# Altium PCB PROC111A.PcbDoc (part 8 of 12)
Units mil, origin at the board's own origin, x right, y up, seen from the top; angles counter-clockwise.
Board outline 7700 x 2300 mil, 6 copper layers (Top Layer, GND 1, SIG 1, SIG 2, GND 2, Bottom Layer), stack 61.062 mil thick; 841 components, 632 nets, 2914 pads, 1627 vias.
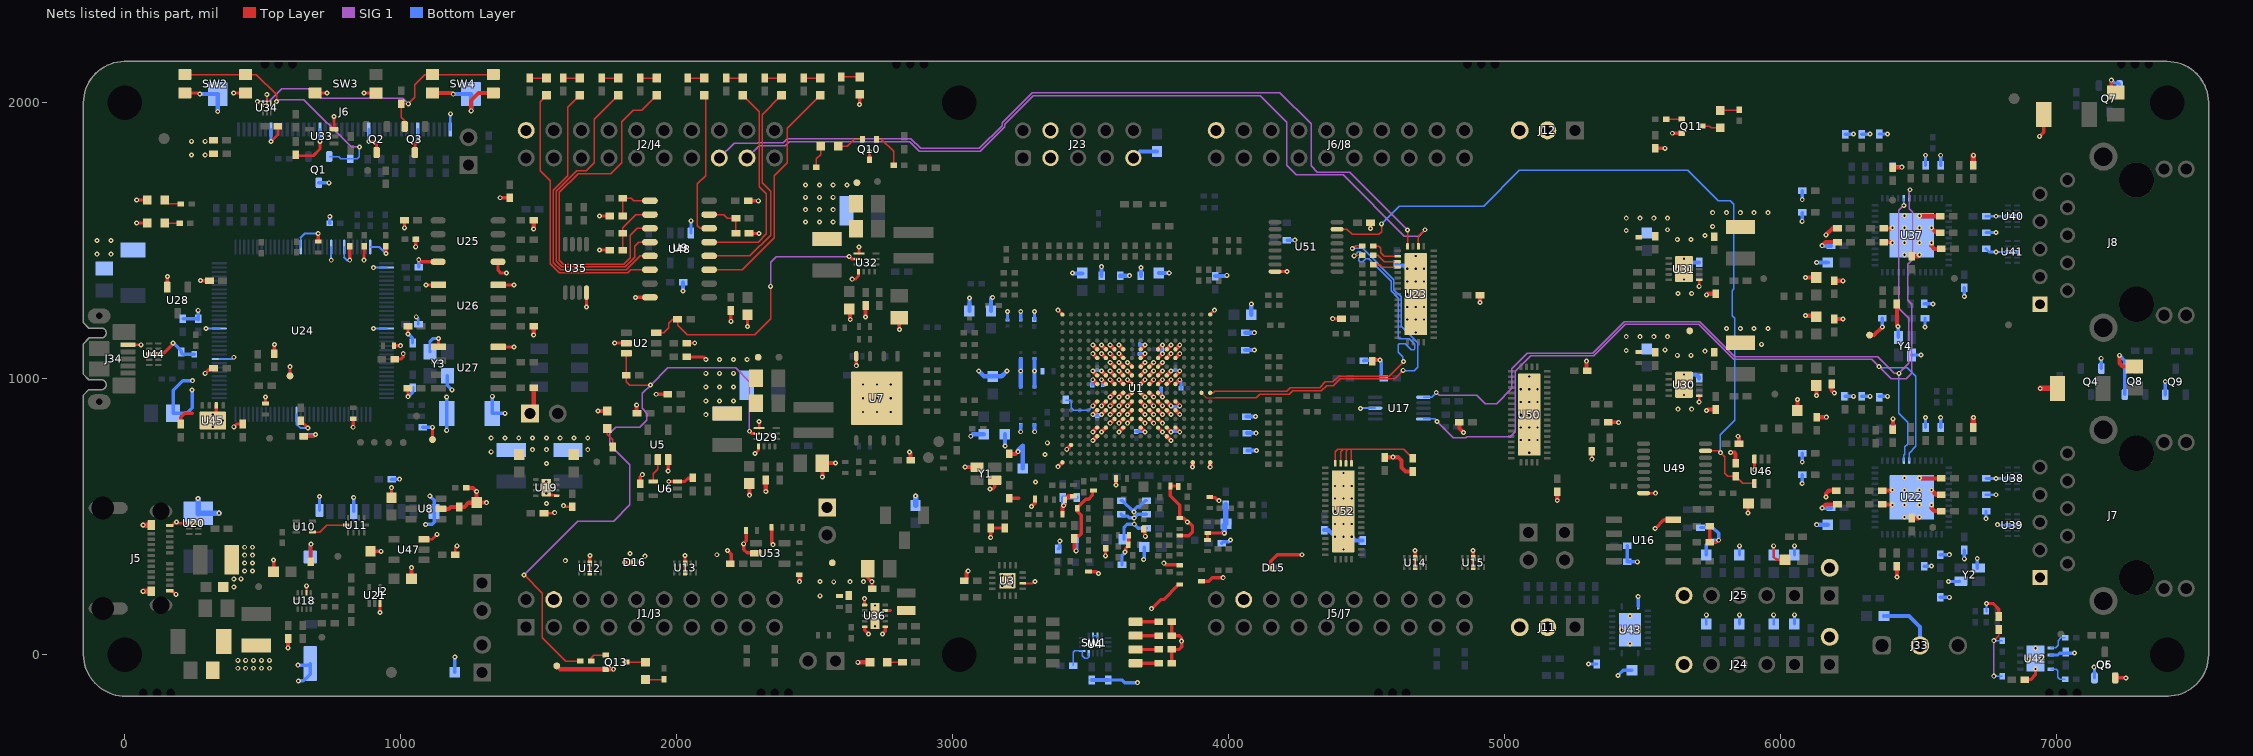
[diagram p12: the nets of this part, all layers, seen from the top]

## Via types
v1: diameter 18, hole 8, Top Layer to Bottom Layer, tented both sides, 1523 vias
v2: diameter 19.68, hole 7.87, Top Layer to Bottom Layer, tented both sides, 104 vias

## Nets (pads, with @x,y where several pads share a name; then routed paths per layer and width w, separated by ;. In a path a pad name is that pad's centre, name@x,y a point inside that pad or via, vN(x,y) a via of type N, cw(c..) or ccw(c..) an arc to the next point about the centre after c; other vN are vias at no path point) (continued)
GND: C1.2 C2.2 C3.2 C4.2 C5.2 C6.2 C7.2 C8.2 C9.2 C10.2 C11.2 C12.2 C13.2 C14.2 C15.2 C16.2 C17.2 C18.2 C19.1 C20.1 C21.1 C22.1 C23.2 C24.2 C25.2 C26.2 C27.2 C28.2 C29.1 C30.1 C31.1 C32.1 C33.2 C34.2 C35.2 C36.2 C37.2 C38.2 C39.1 C40.1 C41.1 C42.1 C43.1 C44.1 C45.1 C46.1 C47.1 C48.2 C49.2 C50.2 C51.2 C52.2 C53.2 C54.2 C55.2 C56.2 C57.1 C58.2 C59.2 C60.1 C61.1 C62.1 C63.2 C64.1 C65.1 C66.1 C67.2 C68.2 C69.2 C70.1 C71.1 C72.1 C73.1 C74.1 C75.1 C81.1 C82.1 C83.1 C84.1 C85.1 C86.1 C87.1 C88.1 C89.2 C90.2 C91.2 C92.1 C93.1 C94.1 C95.1 C96.1 C97.1 C98.2 C99.1 C100.1 C101.2 C102.2 C103.2 C104.2 C105.2 C106.2 C107.2 C108.2 C109.2 C110.2 C111.1 C112.2 C113.2 C114.2 C115.2 C116.2 C117.2 C118.2 C119.2 C120.2 C121.2 C122.2 C123.2 C124.2 C125.2 C126.2 C127.2 C128.2 C129.2 C130.2 C131.2 C132.2 C133.2 C136.1 C137.1 C138.1 C157.2 C158.2 C159.2 C160.2 C161.2 C162.2 C163.2 C164.2 C165.2 C166.2 C167.2 C168.2 C169.2 C170.2 C171.2 C172.2 C173.2 C174.2 C175.2 C176.2 C177.2 C178.2 C179.2 C180.2 C181.1 C182.1 C183.1 C184.1 C185.2 C186.2 C187.2 C188.2 C189.2 C190.2 C191.2 C192.2 C193.2 C194.2 C195.2 C196.2 C197.2 C198.2 C199.2 C200.2 C201.2 C202.2 C203.2 C204.2 C205.2 C206.2 C207.2 C208.2 C209.2 C210.2 C211.2 C212.2 C213.2 C214.2 C215.2 C216.2 C217.2 C218.2 C219.2 C220.2 C221.2 C222.2 C223.1 C224.2 C225.1 C226.1 C229.1 C234.2 C235.1 C236.2 C237.2 C238.1 C239.1 C240.1 C241.1 C242.1 C243.1 C244.1 C245.1 C246.1 C247.1 C248.2 C249.2 C250.2 C251.1 C252.1 C253.2 C254.2 D1.1 D2.1 D4.1 D6.1 D15.2 D16.2 J1/J3.22 J2.6 J2.10 J2.S1 J2.S2 J2.S3 J2.S4 J2/J4.20 J5.A1 J5.A12 J5.B1 J5.B12 J5/J7.62 J6.7 J6.16 J6.25 J6.34 J6.40 J6.41 J6.42 J6/J8.60 J7.1 J8.1 J11.2 J11.3 J12.2 J12.3 J15.2 J16.2 J17.1 J18.1 J23.3 J23.4 J23.9 J24.5 J25.5 J33.2 Q1.3 Q2.3 Q3.3 Q4.2 Q5.2 Q6.2 Q7.2 Q8.2 Q9.2 Q10.3 Q11.2 Q13.2 R2.1 R6.1 R20.2 R21.1 R22.1 R23.1 R24.1 R25.1 R32.2 R39.1 R44.1 R95.1 R96.1 R97.1 R98.2 R107.1 R120.1 R121.1 R122.1 R123.1 R124.1 R125.1 R126.1 R127.1 R128.1 R148.1 R152.1 R154.1 R160.1 R161.1 R163.1 R202.1 R215.1 R216.1 R217.1 R218.1 R219.1 R220.1 R221.1 R222.1 R223.1 R250.1 R254.2 R255.2 R256.1 R274.1 R275.1 R276.1 R278.1 R289.1 R290.1 R293.1 R294.1 R299.2 R300.1 R304.1 R307.1 R316.2 R321.1 R322.1 R323.1 R373.1 R375.1 SW2.1 SW2.3 SW3.1 SW3.3 SW4.1 SW4.3 TP6.1 TP13.1 TP14.1 TP15.1 TP16.1 TP17.1 U1.A1 U1.A18 U1.E5 U1.E6 U1.E7 U1.E8 U1.E10 U1.E12 U1.E13 U1.E14 U1.F5 U1.F6 U1.F7 U1.F8 U1.F10 U1.F12 U1.F13 U1.F14 U1.G7 U1.G8 U1.G9 U1.G10 U1.G11 U1.G12 U1.H5 U1.H6 U1.H7 U1.H8 U1.H9 U1.H10 U1.H11 U1.H12 U1.H13 U1.H14 U1.J5 U1.J6 U1.J7 U1.J8 U1.J9 U1.J10 U1.J11 U1.J12 U1.J13 U1.J14 U1.K7 U1.K8 U1.K9 U1.K10 U1.K11 U1.K12 U1.L5 U1.L6 U1.L7 U1.L8 U1.L9 U1.L10 U1.L11 U1.L12 U1.L13 U1.L14 U1.M5 U1.M6 U1.M7 U1.M8 U1.M9 U1.M10 U1.M11 U1.M12 U1.M13 U1.M14 U1.N7 U1.N8 U1.N9 U1.N10 U1.N11 U1.N12 U1.P5 U1.P6 U1.P8 U1.P10 U1.P12 U1.P13 U1.P14 U1.R5 U1.R13 U1.T2 U1.V1 U1.V16 U1.V18 U2.2 U3.6 U3.17@3198.05,268.7 U4.10 U4.11 U5.3 U6.3 U7.4 U7.9 U8.2 U9.3 U12.3@1685,298.04 U12.8@1685,330.91 U13.3@2030,298.56 U13.8@2030,331.44 U14.3@4675,317.68 U14.8@4675,350.55 U15.3@4885.4,317.82 U15.8@4885.4,350.69 U16.4 U17.3 U18.10 U19.5 U19.9 U20.3@233.41,476.95 U20.8@266.29,476.95 U21.3 U22.49 U23.43 U25.5 U26.4 U27.4 U29.4 U29.7 U30.6 U30.11 U31.6 U31.11 U32.4 U32.7 U33.3 U34.2 U35.4 U36.1 U36.5 U36.6 U36.11@2717.72,141.07 U37.49 U38.3@6856.02,638.94 U38.8@6823.14,638.94 U39.3@6855.75,469.6 U39.8@6822.87,469.6 U40.3@6856.02,1588.94 U40.8@6823.14,1588.94 U41.3@6855.75,1459.6 U41.8@6822.87,1459.6 U42.2 U42.9 U43.11 U43.21 U46.3 U47.3 U48.16 U49.8 U50.43 U51.8 U52.43 U53.2 Y1.2 Y1.4 Y2.2 Y2.4 Y4.2 Y4.4 | length 18831.1
  Top Layer w6: U34.2@515,1996.97 v1@515,2029.53
  Top Layer w7: U18.10@658.07,224.61 v1(658.07,250)
  Top Layer w8: v1(514.53,2030) v1@515,2029.53 ; U3.6@3253.17,258.86 3288.32,258.86 3295.5,266.04 v1(3298.21,266.04)
  Top Layer w10: v1(187.46,481.61) 189.63,481.61 194.29,476.95 U20.3@233.41,476.95 U20.8@266.29,476.95 ; v1(530,1859.61) 555.62,1885.22 C181.1@555.62,1915 ; C182.1@619.3,1808.19 682.83,1808.19 707.17,1832.52 v1(707.17,1859.61) ; v1(925,152.93) U21.3@924.98,185.87 ; v1(965.86,605.32) 965.86,569.53 C67.2@966.44,568.95 ; U47.3@1083.63,418.4 1113.4,418.4 v1(1131.5,436.5) ; R299.2@1197.12,362.5 1197.12,388.62 v1(1203.5,395) ; R98.2@1518.62,513.27 1553.78,513.27 1555.51,515 v1(1557.67,515) ; U19.9@1526.92,605.91 1526.92,592.13 1539.64,579.41 1549.16,579.41 1550.3,578.27 1557.67,578.27 1559.56,576.38 U19.5@1564.33,576.38 ; v1(1590,540.32) 1593.94,536.38 C109.2@1621.58,536.38 ; v1(2283.37,728.82) 2296.36,741.81 U29.7@2296.36,755.26 ; U29.4@2298.33,821.21 v1(2298.33,845.01) ; v1(2635.5,1361) 2647,1361 2658.03,1372.03 U32.7@2658.03,1387.88 ; U32.4@2660,1453.83 v1(2660,1477.63) ; v1(3381.39,1248.54) U1.A1@3397.13,1232.8 ; v1(3553.53,358.51) 3553.58,358.55 R307.1@3553.58,385.13 ; U1.A18@3932.57,1232.8 v1(3948.31,1248.54) ; U51.8@4167.8,1388.35 v1(4210.59,1388.35) ; v1(5315.31,708.62) R289.1@5315.31,737.92 ; U49.8@5502.8,585.66 v1(5545.59,585.66) ; v1(5704.25,915.8) U30.6@5704.25,939.06 ; v1(5704.25,1334.99) U31.6@5704.25,1358.25 ; v1(5974.18,395) 5974.18,354.64 5984.15,344.67 C221.2@6015.63,344.67
  Top Layer w11: J5.A12@163.07,231.89 170.95,231.89 183.61,219.23 v1(185.37,219.23) ; J5.A1@163.07,468.11 170.95,468.11 183.1,480.27 186.12,480.27 v1(187.46,481.61)
  Top Layer w12: SW2.1@217.32,2035.35 267,2035.35 270.21,2032.15 v1(271.83,2032.15) ; v1(394.55,2035.35) SW2.3@437.8,2035.35 ; C101.2@539.29,304.11 v1(539.29,343.25) ; R97.1@673.29,337.04 673.77,337.51 673.77,400.18 v1(674.24,400.65) ; SW3.1@689.76,2035.35 v1(733.01,2035.35) ; U33.3@757.66,1903.74 v1(757.66,1950) ; v1(866.99,2035.35) SW3.3@910.24,2035.35 ; v1(884.33,1859.61) 905,1859.61 912.25,1852.35 Q2.3@912.25,1819.78 ; C110.2@890,375.04 v1(927.78,375.04) ; Q3.3@1051.12,1819.78 1051.14,1849.25 v1(1061.5,1859.61) ; U25.5@1352.36,1423.86 1352.36,1393.52 1362.61,1383.27 v1(1383.19,1383.27) ; U27.4@1353.27,1115.27 v1(1410,1115.27) ; U26.4@1353.27,1340 v1(1410,1340) ; v1(1360,1656) R21.1@1395,1656 ; v1(1672.76,1260.12) U35.4@1672.76,1312.4 ; U12.3@1685,298.04 U12.8@1685,330.91 v1(1685,359.48) ; v1(1720,1466.57) R276.1@1757.31,1466.57 ; v1(1720,1589.85) R274.1@1757.31,1589.85 ; v1(1775,1129.45) U2.2@1817.11,1129.45 ; v1(1810,335.1) D16.2@1834.92,335.1 ; v1(1850.43,1295) U48.16@1902.72,1295 ; C64.1@1867.57,620.1 1867.57,645.11 v1(1875,652.54) ; v1(1925.37,944.07) R20.2@1967.18,944.07 ; v1(1968.71,665.97) U5.3@1968.71,707.27 ; v1(1970.87,627.98) U6.3@2002.96,627.98 2029.73,627.98 2041.61,639.85 2057.84,639.85 C63.2@2057.84,641.01 ; U13.3@2030,298.56 U13.8@2030,331.44 v1(2030,360) ; C57.1@2036.02,1129.45 v1(2065,1129.45) ; R6.1@2036.34,1079.13 2094.97,1079.13 2104.1,1070 v1(2105,1070) ; v1@2183.96,378.38 2197.34,364.99 R375.1@2197.34,330.17 ; v1(2195.94,1208.33) C237.2@2195.94,1247.76 ; C254.2@2251.19,450.13 2251.19,412.43 2242.36,403.61 v1(2242.36,401.98) 2242.36,381.45 2254.39,369.42 2285.58,369.42 U53.2@2287.43,367.57 ; v1(2255.95,1189.91) C236.2@2255.95,1232.01 ; R278.1@2258.62,1645 v1(2295.32,1645) ; R275.1@2261.63,1526.55 v1(2298.33,1526.55) ; C253.2@2343.56,461.96 2343.56,405.03 2348.12,400.47 v1(2348.12,398.85) ; U7.4@2650,1082.08 2650,1047.93 v1(2650.41,1047.52) ; v1(2655.91,-27.34) v1@2656.41,-26.84 ; v1(2662.21,1993.35) 2662.72,1993.87 D4.1@2662.72,2030.75 ; U36.5@2680.31,101.69 2680.7,101.69 2680.7,89.17 v1(2695,74.87) ; U36.1@2680.31,182.8 v1(2680.31,203.41) ; C185.2@2691.5,312.4 2691.5,280 v1(2706.5,265) 2707.19,264.31 2707.19,240.06 C186.2@2707.87,239.37 ; Q10.3@2698,1793.6 v1(2698,1824.32) ; v1(2745,74.87) 2755.12,84.98 U36.6@2755.12,101.69 ; R160.1@2806.47,1220.85 2806.47,1178.5 v1(2806.79,1178.18) ; v1(3135,601.21) 3144.48,601.21 3151.99,608.72 Y1.2@3151.99,632.59 ; v1(3137.35,425.17) 3137.47,425.29 C48.2@3137.47,459.62 R2.1@3187.66,459.62 ; C58.2@3205,567.59 3239.33,567.59 3239.46,567.47 ; C91.2@3440,421.38 3440,425.32 3445.81,431.13 3457.72,431.13 3465.21,438.61 3465.21,505.29 3452.34,518.16 3452.34,529.32 C96.1@3450.84,530.82 ; C96.1@3450.84,532.82 3481.6,563.57 3489.68,563.57 3489.92,563.82 3491.78,563.82 3505.99,578.03 3505.99,593.67 3507.49,595.17 C97.1@3509.8,595.17 ; C251.1@3491.36,301.22 C251.1@3491.62,301.22 3519.2,301.22 3526.22,294.2 v1(3527.84,294.2) ; v1@3590.83,616.61 3590.83,638.44 C93.1@3590.94,638.55 ; v1@3625.31,371.95 3626.45,373.1 3626.45,385.27 3634.1,392.92 3634.1,396.92 C87.1@3635.6,398.42 ; C87.1@3635.6,398.92 3637.1,400.42 3637.1,426.29 3638.81,428 C88.1@3638.81,432.5 ; R44.1@3691.48,454.12 3695.32,450.27 3695.32,432.97 3697.37,430.93 v1(3697.37,429.3) ; v1(3719.97,167.18) 3753.12,200.33 3763.78,200.33 3817.59,254.13 C86.1@3822.09,254.13 ; v1(3764.37,331.78) 3765.99,331.78 3771.77,326 3820.59,326 C81.1@3822.09,324.5 ; R22.1@3793.62,-30.49 R23.1@3793.62,19.51 3819.81,19.51 3828.97,28.67 v1(3828.97,49.16) 3828.43,49.69 3828.43,62.48 3821.4,69.51 R24.1@3793.62,69.51 R25.1@3793.62,119.51 ; C84.1@3816.76,609.98 3815.26,611.49 C82.1@3788.34,611.49 3788.34,575.68 3822.33,541.69 C83.1@3822.33,496.02 3823.83,494.52 3837.54,494.52 3849.25,482.82 v1(3849.64,480.71) ; C74.1@3822.33,431.86 3855.02,431.86 3868.58,445.42 3868.58,465.5 3855.84,478.24 3853.82,478.25 v1(3849.64,480.71) ; v1@3849.25,478.62 v1(3849.64,480.71) ; C85.1@3901.07,266.72 3927.21,266.72 3939.99,279.5 v1(3979.74,279.5) ; C75.1@3922.62,418.13 3922.88,418.4 3922.88,441.3 C72.1@3923.15,441.57 3923.48,441.23 3983.38,441.23 v1(3983.72,440.9) ; C73.1@3931.07,571.48 3932.57,569.98 3949.2,569.98 3959.77,559.4 3963.34,559.4 v1(3964.49,558.25) ; D15.2@4150.71,315.32 4151.6,316.2 4151.6,338.97 4175.15,362.52 v1(4265,362.52) ; v1(4376.3,1217.86) 4376.37,1217.93 R290.1@4408.11,1217.93 ; U14.3@4675,317.68 U14.8@4675,350.55 v1(4675,377.91) ; v1(4885,377.91) 4885.4,377.5 U15.8@4885.4,350.69 U15.3@4885.4,317.82 ; v1@5189.88,559.09 v1(5190,558.97) ; R294.1@5375,842.02 5412.09,842.02 v1(5412.51,841.6) ; v1(5544.94,457.56) 5576.52,489.14 U16.4@5610.08,489.14 ; R304.1@5545.31,1835.02 v1(5580,1835) ; v1(5606.81,1889.68) Q11.2@5640.6,1889.68 ; R323.1@5742.56,465 R321.1@5742.56,406.99 5766.9,406.99 v1(5774.91,415) ; v1(5881.36,513.38) 5881.36,547.14 C248.2@5882.6,548.38 ; v1(5904.41,670.59) U46.3@5904.41,709.29 ; v1(6745,185.87) 6769.4,185.87 6790,165.27 C222.2@6790,138.62 ; C226.1@6883.62,-89.6 6905.4,-89.6 6922.8,-72.2 v2(6922.8,-50.95) ; v1(6937.71,1878.68) 6952.48,1893.44 C247.1@6952.48,1956.97 ; v1(7197.42,2081.89) 7197.42,2053.71 R255.2@7214.16,2036.97 ; Q5.2@7211.4,-83.58 v1(7250,-83.58)
  Top Layer w13: U1.P12@3743.59,823.35 v1(3759.34,807.6) ; U1.P13@3775.09,823.35 v1(3790.83,807.6) ; U1.P14@3806.58,823.35 v1(3822.33,807.6)
  Top Layer w15: R95.1@591.65,58.85 591.71,58.8 591.71,25.37 v1(591.77,25.31) ; C249.2@1038.36,275.41 v1(1038.36,315.6) ; SW4.1@1114.76,2035.35 1185.13,2035.35 1189.19,2031.3 v1(1190,2031.3) ; U8.2@1145.16,528.6 1173.99,528.6 1180.8,535.41 C69.2@1212.1,535.41 1230.37,535.41 1246.06,551.1 1274.7,551.1 C68.2@1274.76,551.16 ; R39.1@1236.92,604.8 1261.3,604.8 1274.76,591.35 C68.2@1274.76,551.16 ; v1(1255,1970.99) 1255,2008.4 1281.95,2035.35 SW4.3@1335.24,2035.35 ; v1(1310.42,551.16) C68.2@1274.76,551.16 ; J17.1@1468.62,873.77 1481.5,886.64 C136.1@1481.5,967.23 ; v1(1481.5,1158.81) C137.1@1481.5,1190 ; v1(1481.5,1542.68) C138.1@1481.5,1573.86 ; TP13.1@1565,-40 1577.2,-52.2 Q13.2@1742.6,-52.2 v1(1771.18,-52.2) ; v1(1714.39,883.2) D2.1@1748.27,883.2 ; v1(1854.54,905.56) 1854.54,875.93 C65.1@1855.6,874.86 ; C160.2@2262.84,620.19 2262.84,578.44 v1(2263.01,578.27) ; R154.1@2322.33,633.06 2322.33,591.32 v1(2322.51,591.14) ; v1(2444.32,265) R373.1@2444.32,290.17 ; v1(2527.33,644.21) R148.1@2527.33,694.68 2574.68,694.68 v1(2575,695) ; C177.2@2624.51,1252.8 2627.87,1249.45 2627.87,1215.22 v1(2628.44,1214.64) ; v1@2656.41,-26.84 D6.1@2700,-26.84 ; R163.1@2684,1265.68 2684,1223.93 v1(2684.18,1223.76) ; v1(2843.31,735.26) 2847.24,731.32 C66.1@2847.24,704.15 ; C60.1@3041.38,268.33 3045.32,268.33 3049.63,272.64 3049.63,297.03 3055.7,303.1 v1(3055.7,303.91) ; v1(3045,680) 3045.16,679.84 Y1.4@3088.01,679.84 ; C59.2@3205,727.96 3227.36,727.96 3235.25,735.85 v1(3236.07,735.85) ; v1(3285.55,537.72) 3285.55,538.53 3297.3,550.27 C92.1@3297.3,564.5 ; v1(3381.39,681.61) U1.V1@3397.13,697.36 ; C252.1@3397.4,508.89 3397.4,535.41 3401.66,539.67 v1(3401.66,540.48) 3401.66,541.29 3406.75,546.38 C94.1@3406.75,562.35 3406.75,566.85 3411.25,566.85 3418.99,574.59 C95.1@3437.53,574.59 ; v1(3412.88,744.61) U1.T2@3428.63,760.35 ; C91.2@3440,421.38 3440.77,420.61 3440.77,383.99 3447.17,377.59 v1(3447.17,376.78) ; v1(3507.37,776.1) U1.R5@3523.12,791.85 ; v1(3507.37,807.6) U1.P5@3523.12,823.35 ; v1(3507.37,870.59) U1.M5@3523.12,886.34 ; v1(3507.37,902.09) U1.L5@3523.12,917.83 ; v1(3507.37,996.57) U1.J5@3523.12,980.83 ; v1(3507.37,1028.07) U1.H5@3523.12,1012.32 ; v1(3507.37,1091.06) U1.F5@3523.12,1075.32 ; v1(3507.37,1122.56) U1.E5@3523.12,1106.81 ; v1(3538.87,807.6) U1.P6@3554.61,823.35 ; v1(3538.87,870.59) U1.M6@3554.61,886.34 ; v1(3538.87,902.09) U1.L6@3554.61,917.83 ; v1(3538.87,996.57) U1.J6@3554.61,980.83 ; v1(3538.87,1028.07) U1.H6@3554.61,1012.32 ; v1(3538.87,1091.06) U1.F6@3554.61,1075.32 ; v1(3538.87,1122.56) U1.E6@3554.61,1106.81 ; v1(3570.36,839.09) U1.N7@3586.11,854.84 ; v1(3570.36,870.59) U1.M7@3586.11,886.34 ; v1(3570.36,902.09) U1.L7@3586.11,917.83 ; v1(3570.36,933.58) U1.K7@3586.11,949.33 ; v1(3570.36,996.57) U1.J7@3586.11,980.83 ; v1(3570.36,1028.07) U1.H7@3586.11,1012.32 ; v1(3570.36,1059.57) U1.G7@3586.11,1043.82 ; v1(3570.36,1091.06) U1.F7@3586.11,1075.32 ; v1(3570.36,1122.56) U1.E7@3586.11,1106.81 ; v1(3601.86,807.6) U1.P8@3617.61,823.35 ; v1(3601.86,839.09) U1.N8@3617.61,854.84 ; v1(3601.86,870.59) U1.M8@3617.61,886.34 ; v1(3601.86,902.09) U1.L8@3617.61,917.83 ; v1(3601.86,933.58) U1.K8@3617.61,949.33 ; v1(3601.86,996.57) U1.J8@3617.61,980.83 ; v1(3601.86,1028.07) U1.H8@3617.61,1012.32 ; v1(3601.86,1059.57) U1.G8@3617.61,1043.82 ; v1(3601.86,1091.06) U1.F8@3617.61,1075.32 ; v1(3601.86,1122.56) U1.E8@3617.61,1106.81 ; v1(3633.35,839.09) U1.N9@3649.1,854.84 ; v1(3633.35,870.59) U1.M9@3649.1,886.34 ; v1(3633.35,902.09) U1.L9@3649.1,917.83 ; v1(3633.35,933.58) U1.K9@3649.1,949.33 ; v1(3633.35,996.57) U1.J9@3649.1,980.83 ; v1(3633.35,1028.07) U1.H9@3649.1,1012.32 ; v1(3633.35,1059.57) U1.G9@3649.1,1043.82 ; U1.P10@3680.6,823.35 v1(3696.35,807.6) ; U1.N10@3680.6,854.84 v1(3696.35,839.09) ; U1.M10@3680.6,886.34 v1(3696.35,870.59) ; U1.L10@3680.6,917.83 v1(3696.35,902.09) ; U1.K10@3680.6,949.33 v1(3696.35,933.58) ; U1.J10@3680.6,980.83 v1(3696.35,996.57) ; U1.H10@3680.6,1012.32 v1(3696.35,1028.07) ; U1.G10@3680.6,1043.82 v1(3696.35,1059.57) ; U1.F10@3680.6,1075.32 v1(3696.35,1091.06) ; U1.E10@3680.6,1106.81 v1(3696.35,1122.56) ; U1.N11@3712.09,854.84 v1(3727.84,839.09) ; U1.M11@3712.09,886.34 v1(3727.84,870.59) ; U1.L11@3712.09,917.83 v1(3727.84,902.09) ; U1.K11@3712.09,949.33 v1(3727.84,933.58) ; U1.J11@3712.09,980.83 v1(3727.84,996.57) ; U1.H11@3712.09,1012.32 v1(3727.84,1028.07) ; U1.G11@3712.09,1043.82 v1(3727.84,1059.57) ; U1.N12@3743.59,854.84 v1(3759.34,839.09) ; U1.M12@3743.59,886.34 v1(3759.34,870.59) ; U1.L12@3743.59,917.83 v1(3759.34,902.09) ; U1.K12@3743.59,949.33 v1(3759.34,933.58) ; U1.J12@3743.59,980.83 v1(3759.34,996.57) ; U1.H12@3743.59,1012.32 v1(3759.34,1028.07) ; U1.G12@3743.59,1043.82 v1(3759.34,1059.57) ; U1.F12@3743.59,1075.32 v1(3759.34,1091.06) ; U1.E12@3743.59,1106.81 v1(3759.34,1122.56) ; U1.R13@3775.09,791.85 v1(3790.83,776.1) ; U1.M13@3775.09,886.34 v1(3790.83,870.59) ; U1.L13@3775.09,917.83 v1(3790.83,902.09) ; U1.J13@3775.09,980.83 v1(3790.83,996.57) ; U1.H13@3775.09,1012.32 v1(3790.83,1028.07) ; U1.F13@3775.09,1075.32 v1(3790.83,1091.06) ; U1.E13@3775.09,1106.81 v1(3790.83,1122.56) ; U1.M14@3806.58,886.34 v1(3822.33,870.59) ; U1.L14@3806.58,917.83 v1(3822.33,902.09) ; U1.J14@3806.58,980.83 v1(3822.33,996.57) ; U1.H14@3806.58,1012.32 v1(3822.33,1028.07) ; U1.F14@3806.58,1075.32 v1(3822.33,1091.06) ; U1.E14@3806.58,1106.81 v1(3822.33,1122.56) ; v1(3868.57,680.7) 3868.57,681.52 3869.43,682.38 3869.43,697.22 U1.V16@3869.57,697.36 ; U1.V18@3932.57,697.36 3932.65,697.28 3932.65,680.79 v1(3932.73,680.7) ; C246.1@4513.43,1567.48 4513.66,1567.25 4513.66,1544.97 v1(4513.89,1544.74) ; C240.1@4520.38,1063.22 4520.38,1063.7 4524.69,1068.01 4547.7,1068.01 v1(4548.27,1068.58) ; C245.1@4565,714.8 4566.1,715.9 v1(4595,715.9) 4613.67,715.9 4626.02,703.55 4626.02,678.46 4640.08,664.4 R256.1@4666.77,664.4 ; C111.1@4835.38,842.82 4835.38,819.7 v1(4850,805.08) ; v1(4910,1276.95) C242.1@4910,1301.95 ; v1@5189.88,559.09 C239.1@5189.88,591.15 ; C238.1@5295.86,1029.87 v1(5295.86,1063.79) ; v1(5730.69,885) 5731.5,885 5735.23,888.74 R152.1@5764.13,888.74 ; v1(5730.69,1304.19) 5731.5,1304.19 5735.23,1307.92 R161.1@5764.13,1307.92 ; v1(5818.5,732.8) 5831.65,732.8 5836.5,727.96 R96.1@5836.5,693.62 ; v1(5844.69,791.85) 5848.62,787.91 C43.1@5848.62,764.8 ; C122.2@6060,885.15 v1(6060,925.06) ; v1(6090,1229.35) 6090.74,1228.61 C114.2@6129,1228.61 ; v1(6090,1367.45) 6090.74,1366.71 C191.2@6129,1366.71 ; v1(6128.93,939.06) C199.2@6128.93,975.48 ; C123.2@6130.09,860.77 v1(6165,860.77) ; v1(6150,532.33) 6162.71,545.04 C133.2@6205.51,545.04 ; v1(6150,1482.33) 6162.71,1495.04 C210.2@6205.51,1495.04 ; v1(6163.62,571.81) 6163.62,585 6173.66,595.04 C119.2@6200.51,595.04 ; v1(6163.62,1521.81) 6186.85,1545.04 C196.2@6205.51,1545.04 ; C200.2@6184,981.36 6184,958.26 v1(6194,948.26) ; C115.2@6194,1216.9 6224.83,1216.9 v1(6225,1217.07) ; C192.2@6194,1355 6224.83,1355 v1(6225,1355.17) ; TP16.1@6321.65,1158.13 6338.28,1158.13 v1(6367.76,1187.61) ; C132.2@6367.56,545.04 6401.07,545.04 6403.04,543.07 v2(6404.31,543.07) ; C118.2@6367.56,595.04 6402.34,595.04 v2(6404.31,597.01) ; C209.2@6372.56,1495.04 6402.34,1495.04 v2(6404.31,1493.07) ; C195.2@6372.56,1545.04 6402.34,1545.04 v2(6404.31,1547.01) ; C116.2@6406.28,818.7 v1(6406.28,855) ; C193.2@6406.28,1765.34 6436.92,1765.34 v1(6438.38,1766.8) ; v1(6420.85,281.38) R126.1@6420.85,321.38 ; R221.1@6420.97,1271.26 6420.97,1193.94 v1(6425,1189.91) ; C130.2@6475,494.09 6497.07,494.09 v2(6502.14,499.17) ; C207.2@6475,1444.09 6497.07,1444.09 v2(6502.14,1449.17) ; v2(6502.14,640.91) 6504.11,638.94 C126.2@6581.79,638.94 ; v2(6502.14,1590.91) 6504.11,1588.94 C203.2@6577.79,1588.94 ; v2(6546.04,543.07) 6546.04,530.77 6555.98,520.83 C124.2@6581.79,520.83 ; v2(6546.04,597.01) 6563.17,579.88 C120.2@6581.79,579.88 ; v2(6546.04,1493.07) 6546.04,1480.77 6555.98,1470.83 C201.2@6581.79,1470.83 ; v2(6546.04,1547.01) 6563.17,1529.88 C197.2@6577.79,1529.88 ; v1(7227.27,1085) 7227.27,1056.56 7238.83,1045 R254.2@7280.57,1045
  Top Layer w20: v1(66.53,229.92) J5.B1@96.14,229.92 ; v1(66.53,470.08) J5.B12@96.14,470.08 ; R123.1@6698,823.31 v1(6698,859.61) ; R218.1@6698,1773.31 v1(6698,1809.61) ; v1(6940,965) C235.1@7002.32,965
  Bottom Layer w5.3: C250.2@3409.37,924.52 3411.4,922.5 3424.84,922.5 3428.67,918.66 3428.67,896.58 3428.73,896.52 3428.73,895.6 3437.89,886.44 3482.36,886.44 3482.43,886.51 3491.79,886.51 v1(3507.37,902.09)
  Bottom Layer w6: v1(3524.36,36.33) 3519.49,36.33 3518.82,37.01 3513.2,37.01 3508.2,42.02 U4.10@3508.2,69.28 U4.11@3523.95,69.28 3523.95,37.27 v1@3524.36,36.85
  Bottom Layer w8: v1(4477.36,892.24) 4478.87,893.75 U17.3@4530.08,893.75 ; R250.1@6745,157.24 v1(6745,185.87) ; v1(6780,1459.6) U41.8@6822.87,1459.6 U41.3@6855.75,1459.6
  Bottom Layer w10: J6.7@529.88,1903.35 529.88,1859.73 v1(530,1859.61) ; J6.16@707.05,1903.35 707.05,1859.73 v1(707.17,1859.61) ; J6.25@884.21,1903.35 884.21,1859.73 v1(884.33,1859.61) ; J6.34@1061.38,1903.35 1061.38,1859.73 v1(1061.5,1859.61) ; J6.40@1179.49,1903.35 1179.49,1959.49 v1(1180,1960) ; C211.2@5730,111.5 v1(5730,145) ; C216.2@5850,111.5 v1(5850,145) ; C219.2@5850,361.5 v1(5850,395) ; C215.2@5974.18,111.5 v1(5974.18,145) ; C218.2@5974.18,361.5 v1(5974.18,395) ; C214.2@6049.18,111.5 v1(6049.18,145) ; C217.2@6049.18,361.5 v1(6049.18,395) ; v1(6743.84,493.12) C125.2@6743.84,520.83 ; C121.2@6743.84,579.88 v1(6780,579.88) ; C127.2@6743.84,638.94 v1(6780,638.94) U38.8@6823.14,638.94 U38.3@6856.02,638.94 ; C202.2@6743.84,1470.83 6755.06,1459.6 v1(6780,1459.6) ; C198.2@6743.84,1529.88 v1(6780,1529.88) ; C204.2@6743.84,1588.94 v1(6780,1588.94) U40.8@6823.14,1588.94 U40.3@6856.02,1588.94 ; v1(6785,471.55) 6787.16,471.55 6789.12,469.6 U39.8@6822.87,469.6 U39.3@6855.75,469.6
  Bottom Layer w12: v1(627.94,-37.71) 665.83,-37.71 J2.S3@671.97,-31.57 671.97,-67.88 671.91,-67.94 671.91,-71.01 654.35,-88.57 651.28,-88.57 645.97,-93.88 629.96,-93.88 v1(628.81,-95.03) ; J2.S2@671.97,354.25 671.97,396.76 674.24,399.03 v1(674.24,400.65) ; Q1.3@702.98,1710.51 739.49,1710.51 v1(740,1710) ; J2.10@705.43,523.54 v1(705.43,573.39) ; J2.6@829.45,519.61 v1(829.45,569.45) ; C71.1@965.09,635 966.5,636.41 v1(995.46,636.41) ; v1(1090.34,471.73) 1091.49,472.88 1113.67,472.88 1120.79,480 J2.S1@1120.79,519.61 1120.79,559.21 v1(1105,575) ; J2.S4@1195.59,-63.07 v1@1195.59,-8.02 ; v1(1331.54,936.51) C234.2@1331.54,875 v1(1377.39,875) ; U9.3@2051.37,1528.43 v1@2051.37,1572.46 ; C42.1@3198.24,1215.28 v1(3198.24,1243.66) ; v1(3245.84,808.19) C45.1@3245.84,831.57 ; C21.1@3245.84,1215.28 3245.84,1243.26 v1(3246.24,1243.66) ; C49.2@3295.84,1215.28 3295.84,1243.26 v1(3296.24,1243.66) ; v1(3296.24,1027.95) v1@3296.46,1027.95 ; C38.2@3381.39,383.27 3386.42,388.3 3386.42,410.91 v1(3387.57,412.06) ; C54.2@3504.78,978.1 3504.78,993.99 v1(3507.37,996.57) ; v1(3507.37,870.59) 3510.59,867.37 C56.2@3523,867.37 3535.64,867.37 v1(3538.87,870.59) ; v1(3507.37,1028.07) 3509.37,1030.07 3536.86,1030.07 v1(3538.87,1028.07) ; v1(3538.87,996.57) 3543.17,992.27 C46.1@3543.17,978.1 ; C62.1@3563.69,-91.65 3613.93,-91.65 3623.27,-100.99 v1(3669.32,-100.99) ; C34.2@3610,508.97 3615.81,503.16 3632.43,503.16 3638.63,496.96 3655.92,496.96 v1(3657.07,495.81) 3670.23,508.97 C27.2@3701.69,508.97 ; C36.2@3610,558.97 3613.94,558.97 3655.43,517.48 v1(3656.29,517.48) ; C37.2@3613,326.8 3613,358.02 3625.31,370.33 v1@3625.31,371.95 ; C33.2@3620.38,419.08 3620.38,462.34 3631.18,473.14 v1(3657.41,473.14) 3671.58,458.97 C26.2@3701.69,458.97 ; v1@3657.61,525.07 3668.72,536.19 3674.97,536.19 3697.75,558.97 C28.2@3701.69,558.97 ; C50.2@3664.85,809.09 3694.85,809.09 v1(3696.35,807.6) ; v1@3692.56,344.91 3693.5,345.86 C25.2@3693.5,390.45 ; C22.1@3754.97,965.08 3754.97,937.95 v1(3759.34,933.58) ; v1(3759.34,1091.06) 3755.95,1094.45 C51.2@3755.95,1107.37 3755.95,1119.18 v1(3759.34,1122.56) ; v1(3790.83,807.6) 3793.24,810.01 3819.92,810.01 v1(3822.33,807.6) ; v1(3790.83,902.09) 3794.25,898.67 C47.1@3806.58,898.67 ; v1(3790.83,1028.07) 3792.84,1030.07 3820.33,1030.07 v1(3822.33,1028.07) ; C47.1@3806.58,897.9 C47.1@3806.58,898.67 ; v1(3822.33,902.09) 3818.91,898.67 C47.1@3806.58,898.67 ; v1(3822.33,996.57) 3827.01,991.9 C55.2@3827.01,965.08 ; C24.2@3974.58,404.26 3980.39,410.07 3999.45,410.07 4004.97,415.59 v1(4006.59,415.59) ; R300.1@4212.13,1502.52 v1(4239.19,1502.52) ; R293.1@4488.88,1065.33 4490.98,1067.44 4547.12,1067.44 v1(4548.27,1068.58) 4548.27,1066.96 4552.87,1062.36 4552.87,1007.87 4558.68,1002.06 C100.1@4561.38,1002.06 ; v1(5302.83,-33.58) C223.1@5333.66,-33.58 ; v1(5410,-75) 5428.47,-56.53 C224.2@5460.55,-56.53 ; R316.2@5443.62,395.04 C99.1@5443.62,337.03 v1(5480,337.03) ; U43.11@5483.19,175.27 v1(5483.19,211.28) ; R322.1@5708.93,461.02 5753.98,461.02 5774.91,440.09 v1(5774.91,415) 5745.93,415 5730,399.07 C212.2@5730,361.5 ; v1(6077.6,620.73) 6077.68,620.81 R120.1@6077.68,652.65 ; v1(6077.6,1570.73) 6077.68,1570.81 R215.1@6077.68,1602.65 ; v1(6077.68,699.04) 6077.76,699.12 R121.1@6077.76,730.96 ; v1(6077.68,1649.04) 6077.76,1649.12 R216.1@6077.76,1680.96 ; v1(6130,1421.55) v1@6130.31,1421.24 ; v1(6150,1482.33) v1@6150.37,1481.97 ; R127.1@6233.01,936.59 6263.24,936.59 v1(6263.32,936.51) ; R222.1@6233.01,1886.59 6263.24,1886.59 v1(6263.32,1886.51) ; R128.1@6293.01,936.59 6323.24,936.59 v1(6323.32,936.51) ; R223.1@6293.01,1886.59 6323.24,1886.59 v1(6323.32,1886.51) ; R125.1@6356.28,936.67 6386.51,936.67 v1(6386.59,936.59) ; R217.1@6356.28,1886.67 6386.51,1886.67 v1(6386.59,1886.59) ; v1(6367.76,1187.61) C189.2@6367.76,1220 ; C117.2@6406.28,818.7 v1(6406.28,855) ; C194.2@6406.28,1768.7 6434.85,1768.7 6436.75,1766.8 v1(6438.38,1766.8) ; v1(6425,1189.91) 6425,1151.78 Y4.2@6426.38,1150.4 ; Y4.4@6473.62,1086.42 6473.81,1086.24 v1(6508.19,1086.24) ; C131.2@6520,321.38 v1(6546.04,321.38) ; C208.2@6520,1271.38 v1(6551.84,1271.38) ; v1(6522.24,1187.61) C190.2@6522.24,1220 ; R124.1@6524.39,823.7 v1(6524.39,860) ; R219.1@6524.39,1773.7 v1(6524.39,1810) ; C112.2@6578.01,208.25 v1(6610.4,208.25) ; C113.2@6578.01,362.74 v1(6610.4,362.74) ; R122.1@6579.39,823.7 v1(6579.39,860) ; R220.1@6579.39,1773.7 v1(6579.39,1810) ; v1(6608.1,265.5) 6646.23,265.5 Y2.2@6647.61,266.88 ; v1(6665,347.91) R107.1@6665,379.75 ; v1(6665,1297.91) R202.1@6665,1329.75 ; Y2.4@6711.59,314.12 6711.77,314.31 v1(6711.77,348.69) ; U42.2@6977.91,-0.75 7003.38,-0.75 7010.27,6.14 v1(7063.78,6.14) ; v1(7135,-45) 7135,-46.62 7136.6,-48.22 Q6.2@7136.6,-83.58 ; v1(7160.69,1074.19) 7161.5,1073.38 Q4.2@7161.5,1037.24 ; v1(7197.42,2081.89) 7197.42,2081.82 7207.45,2071.79 7221.59,2071.79 7227.4,2065.98 Q7.2@7227.4,2062.24 ; v1(7227.27,1085) 7246.47,1065.8 Q8.2@7246.47,943.42 ; Q9.2@7392.92,942.15 v1(7392.92,990)
  Bottom Layer w15: v1(271.83,2032.15) 336.12,2032.15 J6.42@336.97,2031.3 336.97,1968.74 v1(336.83,1968.6) ; v1(1190,2031.3) J6.41@1254.29,2031.3 1255.14,2030.45 1255.14,1971.13 v1(1255,1970.99) ; v1(2022.21,1317.82) C70.1@2022.21,1349.2 ; C53.2@3060,1246.25 3060.5,1246.75 v1@3060.5,1285.42 ; v1(3065,791.85) 3072.44,799.29 C2.2@3112.14,799.29 ; v1(3093.98,1027.95) 3112.59,1009.34 3143.76,1009.34 C52.2@3145,1008.1 3146.24,1009.34 3177.41,1009.34 v1(3196.02,1027.95) ; C3.2@3138.51,1246.25 3138.51,1292.01 3141.5,1295 v1(3144.5,1295) ; C1.2@3188.57,799.29 3188.57,757.5 v1(3189.76,756.31) ; v1(3236.07,735.85) 3236.07,741.01 3253.5,758.44 C14.2@3253.5,674.72 ; C40.1@3246.24,972.3 v1(3246.24,1027.95) C44.1@3246.24,1071.06 ; C20.1@3295.84,831.57 3295.84,809.97 3296.81,809 v1(3296.81,808.19) ; v1(3296.24,1027.95) C32.1@3296.24,1071.33 ; C29.1@3296.46,971.9 v1@3296.46,1027.95 ; v1(3401.66,540.48) 3401.66,541.29 3398.76,544.19 3398.76,569.99 C15.2@3398.63,570.13 C7.2@3448.63,570.13 ; v1(3433.43,1382.95) 3435.05,1382.95 3436.44,1381.55 C6.2@3469.13,1381.55 ; C90.2@3445,421.29 3447.17,419.11 v1(3447.17,376.78) ; C61.1@3503.69,-91.65 C62.1@3563.69,-91.65 ; C16.2@3538.87,1373.53 v1(3538.87,1406.28) ; C10.2@3606.08,1373.53 v1(3640,1373.53) ; J23.9@3654.17,1800 3677.68,1823.5 C213.2@3740,1823.5 ; C31.1@3677.84,1089.57 3694.04,1089.57 3695.53,1091.06 v1(3696.35,1091.06) ; C30.1@3677.99,1123.75 3679.18,1122.56 v1(3696.35,1122.56) ; C11.2@3681.66,1373.53 v1(3681.66,1403.28) ; C5.2@3746.57,1382.99 3746.79,1383.2 3783.93,1383.2 v1(3784.14,1383.42) ; C12.2@3950.67,1371.84 3989,1371.84 3991.96,1374.8 v1(3992.77,1374.8) ; C18.2@4059.8,1104.06 v1(4092.55,1104.06) ; C13.2@4059.8,1167.07 v1(4092.55,1167.07) ; C17.2@4064.47,863.32 v1(4097.22,863.32) ; C8.2@4065.8,802.97 v1(4098.55,802.97) ; C9.2@4067.29,740 v1(4100.04,740) ; C4.2@4081.5,1231.81 v1(4081.5,1271.38) ; C243.1@4345.23,451.69 4360.67,451.69 v2(4384.49,427.87) ; v2(4445.51,427.87) 4459.31,414.07 C244.1@4485,414.07 ; C241.1@4608.25,1415.37 4608.25,1414.77 4612.56,1410.46 4632.72,1410.46 4643.65,1399.52 4645.8,1399.52 v2(4646.69,1398.62) ; v2(5649.13,1015.84) 5690.47,1015.84 5696,1010.3 5699.93,1010.3 5704.25,1005.99 C166.2@5704.25,1002.06 ; v2(5649.13,1435.02) 5662.76,1421.39 5704.25,1421.39 C178.2@5704.25,1421.24 ; v1(6130,471.55) 6130.31,471.24 C128.2@6169.86,471.24 ; v1@6130.31,1421.24 C205.2@6169.86,1421.24 ; v1(6150,532.33) 6150.37,531.97 C129.2@6181.89,531.97 ; v1@6150.37,1481.97 C206.2@6181.89,1481.97 ; C220.2@6373.66,140.82 6464.35,140.82 6504.17,100.99 J33.2@6504.17,33.86
  Bottom Layer w20: D1.1@265.72,511.91 v1(265.72,566) ; D1.1@265.82,512.94 v1(341.67,512.94) ; C89.2@2865,541.5 v1(2865,575) ; v1(3983.72,440.9) 3983.72,469.2 C23.2@3989.44,474.92 C35.2@3989.44,543.51
  other v1: 409.45,-48.68 438.11,-48.68 466.77,-48.68 495.43,-48.68 524.1,-48.68 409.45,-20.02 438.11,-20.02 466.77,-20.02 495.43,-20.02 524.1,-20.02 1195.72,-8.21 2518.85,213.58 395,245.67 2568.68,264.31 2518.68,265.31 2627.83,265 2676.41,265 395,274.33 421.27,275.31 434.48,303.65 463.14,303.65 434.48,332.31 463.14,332.31 1595.98,340.87 3691.56,344.91 1885,357.3 434.48,360.97 463.14,360.97 2145,362.52 1830,367.53 3624.31,372.95 2183.76,378.38 434.48,389.63 463.14,389.63 1527.39,548.66 1274.81,591.4 3591.01,615.72 3300,626.33 1527.39,693.3 3334.5,725.36 1327.39,735.51 1477.39,743.3 1527.39,743.3 1677.39,743.3 3342.53,768.09 1327.39,785.51 1377.39,785.51 1427.39,785.51 1477.39,785.51 1527.39,785.51 1577.39,785.51 1627.39,785.51 1677.39,785.51 2105,870 2675,879.5 2725,879.5 2775,879.5 5627.2,890 5677.2,890 2105,920 2155,920 2205,920 2675,929.5 2725,929.5 2775,929.5 2105,970 2155,970 2205,970 2675,979.5 2725,979.5 2775,979.5 2105,1020 2155,1020 2205,1020 2155,1070 2205,1070 2255,1070 5625,1085 5675,1085 5725,1100 5440,1102.62 5580,1105 5930,1125 5440,1152.62 5490,1152.62 5540,1152.62 5590,1152.62 5803.33,1182.62 5853.33,1182.62 5903.33,1182.62 5953.33,1182.62 3060.5,1292.5 5627.2,1309.19 5677.2,1309.19 5625,1504.19 5675,1504.19 5725,1519.19 5440,1536.81 5590,1540 5753.33,1551.81 2466.67,1567.62 2516.67,1567.62 2566.67,1567.62 2051.31,1572.52 5440,1581.81 5490,1581.81 5540,1581.81 5590,1581.81 5753.33,1601.81 5803.33,1601.81 5853.33,1601.81 5903.33,1601.81 5953.33,1601.81 2466.67,1612.62 2516.67,1612.62 2566.67,1612.62 2466.67,1657.62 2516.67,1657.62 2566.67,1657.62 2466.67,1702.62 2516.67,1702.62 2566.67,1702.62 2616.67,1702.62 241.4,1810.39 291.4,1810.39 241.4,1860.39 291.4,1860.39
  other v2: 6900.16,-13.54 6945.43,-13.54 6922.8,23.86 5453.66,40.43 5423.15,90.62 5484.17,90.62 2717.72,103.66 2717.72,141.06 5453.66,140.82 2717.72,178.47 3179.35,250 3216.75,250 3179.35,287.4 3216.75,287.4 4415,381.81 4415,427.87 4384.49,473.94 4415,473.94 4445.51,473.94 6448.21,499.17 4384.49,520 4415,520 4445.51,520 6448.21,543.07 6502.14,543.07 4384.49,566.06 4415,566.06 4445.51,566.06 1526.92,584.25 6448.21,597.01 6502.14,597.01 4384.49,612.13 4415,612.13 4445.51,612.13 1526.92,627.56 6448.21,640.91 4415,658.19 5088.39,731.85 5057.87,777.91 5088.39,777.91 5118.9,777.91 5057.87,823.97 5088.39,823.97 5118.9,823.97 5057.87,870.04 5088.39,870.04 5118.9,870.04 5057.87,916.1 5088.39,916.1 5118.9,916.1 5649.13,941.03 5057.87,962.16 5088.39,962.16 5118.9,962.16 5626.49,978.43 5671.77,978.43 5088.39,1008.22 4677.2,1168.31 4646.69,1214.37 4677.2,1214.37 4707.72,1214.37 4646.69,1260.44 4677.2,1260.44 4707.72,1260.44 4646.69,1306.5 4677.2,1306.5 4707.72,1306.5 4646.69,1352.56 4677.2,1352.56 4707.72,1352.56 5649.13,1360.22 5626.49,1397.62 5671.77,1397.62 4677.2,1398.62 4707.72,1398.62 4677.2,1444.69 6448.21,1449.17 6448.21,1493.07 6502.14,1493.07 6448.21,1547.01 6502.14,1547.01 6448.21,1590.91
GND_XDS: C134.1 C135.1 C139.1 C140.1 C141.1 C142.2 C143.1 C144.1 C145.1 C146.2 C147.1 C148.2 C149.2 C150.1 C151.1 C152.1 C153.1 C154.1 C155.1 C156.2 C227.2 C230.1 C231.2 C232.2 C233.1 C234.1 D3.1 DS3.1 J34.5 R137.1 R145.1 R252.1 R253.2 R261.2 R308.2 R309.2 R310.2 TP24.1 TP26.1 U24.10 U24.17 U24.48 U24.55 U24.58 U24.64 U24.66 U24.80 U24.114 U25.4 U26.5 U27.5 U28.2 U44.3@121.44,1088.92 U44.8@88.56,1088.92 U45.6 U45.9@318.69,848.32 Y3.2 Y3.4 | length 2785.9
  Top Layer w8: J34.5@11.81,1123.37 58.68,1123.37 v1(58.94,1123.11) v1@60,1123.11
  Top Layer w12: v1(43.02,1564.76) D3.1@81.52,1564.76 ; v1(43.02,1647.79) DS3.1@81.52,1647.79 ; U44.8@88.56,1088.92 U44.3@121.44,1088.92 136.77,1088.92 v1@175,1127.15 ; U28.2@154.1,1332 154.1,1370.01 v1(155,1370.91) ; v1(174.9,1129.75) v1@175,1129.65 ; C231.2@202.83,835.89 202.83,861.2 216.63,875 245,875 ; v1(274.55,1355.66) C150.1@306.88,1355.66 ; v1(291.26,1020) 309.73,1038.47 C145.1@321.69,1038.47 ; U45.9@318.69,848.32 331.48,861.12 U45.6@331.48,903.44 ; v1(395,826.17) 404.72,835.89 C233.1@427.56,835.89 ; C232.2@510,910.15 510,933.82 v1(510.2,934.01) ; R252.1@541.97,1090.79 v1(541.97,1124.26) ; TP24.1@598.48,1010.35 v1(598.48,1043.83) ; C147.1@637.63,847.6 v1(663.07,822.16) ; C155.1@648.6,791.85 648.79,792.03 684.53,792.03 v1(690.5,798) ; C148.2@700.81,1497.63 v1(700.81,1526.55) ; v1(815,1429.87) R261.2@815,1480.31 ; v1(827.49,824.51) C146.2@827.49,855.32 ; v1(866.99,1429.87) R308.2@866.99,1480.31 ; v1(945.89,1453.83) R309.2@945.89,1480.31 ; C156.2@975,1120 v1(999.04,1120) ; C153.1@978.62,1071.57 1000.33,1071.57 1008.9,1080.14 v1(1008.9,1090.98) ; v1(1013.31,1547.01) C141.1@1013.31,1573.86 ; v1(1026.17,935.27) C139.1@1026.17,965.27 ; v1(1026.17,1162.74) C140.1@1026.17,1190 ; v1(1054,1478.35) 1054.28,1478.63 R310.2@1054.28,1506.39 ; v1(1065.02,1431.46) 1072.61,1423.86 U25.4@1135.36,1423.86 ; v1(1091.37,1340) U26.5@1136.73,1340 ; TP26.1@1115,779.89 v1(1115,824.22) ; U27.5@1136.73,1115.27 v1(1136.73,1146.18)
  Bottom Layer w7: v1@294.89,1182.24 U24.17@342.35,1182.24 ; U24.10@342.35,1072.01 v1@389.81,1072.01 ; 621.88,836.47 U24.114@621.88,871.22 ; U24.48@637.63,1477.52 637.63,1511.88 ; v1@747.86,1430.06 U24.55@747.86,1477.52 ; 795.11,1439.53 U24.58@795.11,1477.52 ; U24.64@889.59,1477.52 922.2,1477.52 ; v1@901.19,1182.24 U24.80@948.65,1182.24 ; v1@901.19,1402.72 U24.66@948.65,1402.72
  Bottom Layer w8: v1(294.7,1182.06) v1@294.89,1182.24 ; v1@389.81,1072.01 395,1077.2 v1(395,1078.07) ; 621.88,836.47 636.19,822.16 v1(663.07,822.16) ; 637.63,1511.88 652.3,1526.55 v1(700.81,1526.55) ; v1@747.86,1430.06 v1(748.05,1429.87) ; 795.11,1439.53 804.76,1429.87 v1(815,1429.87) ; v1(901,1182.06) v1@901.19,1182.24 ; v1(901,1402.53) v1@901.19,1402.72 ; 922.2,1477.52 v1(945.89,1453.83)
  Bottom Layer w10: v1(1056,1224.46) 1062.81,1217.65 C149.2@1062.81,1197.99
  Bottom Layer w12: v1(174.9,1129.75) 176.3,1129.75 205,1101.05 C135.1@205,1097.11 205,1094.98 210.81,1089.17 R137.1@251.47,1089.17 ; C151.1@210.82,1217.4 261.88,1217.4 C152.1@265.82,1213.46 ; v1(243.98,959.49) 243.98,894.63 224.15,874.79 C227.2@175,874.79 176.08,875.88 176.08,958.64 210.55,993.11 v1(245,993.11) ; C152.1@265.82,1217.4 v1(265.82,1248.11) ; C154.1@648.6,791.85 654.75,798 v1(690.5,798) ; R145.1@742.1,1563.62 742.38,1563.9 742.38,1587.58 v1(742.66,1587.87) ; v1(1026.17,935.27) 1042.83,951.93 1042.83,967.59 C143.1@1042.72,967.71 ; v1(1026.17,1162.74) 1042.72,1146.18 C144.1@1042.72,1129.75 ; C142.2@1064.98,1404.93 v1@1065,1431.44 ; C134.1@1079.12,824.22 v1(1115,824.22) ; Y3.4@1105.64,1097.63 1105.64,1135 1116.82,1146.18 v1(1136.73,1146.18) ; v1(1166.18,813.49) C234.1@1166.18,875 v1(1166.18,933.58) ; Y3.2@1168.63,1011.01 1168.63,976.37 v1(1185,960)
  other v1: -100.21,1451.4 -50.21,1451.4 -100.21,1501.4 -50.21,1501.4
  other v2: 318.69,825.68 281.29,848.32 356.09,848.32 318.69,870.96
INT1_PB: Q3.2 R181.1 SW4.2 SW4.4 U34.3 | length 1105.8
  Top Layer w4: v1(480,2005) 488.03,1996.97 U34.3@501.22,1996.97
  Top Layer w5.3: Q3.2@1013.72,1914.27 1013.72,1935.68 1001.5,1947.89 R181.1@1001.5,1996.38 v1(1027.09,1996.38) 1050,2019.29 1050,2066 1086.28,2102.28 SW4.2@1114.76,2102.28 SW4.4@1335.24,2102.28
  SIG 1 w4.75: v1(480,2005) 522.78,2005 569.17,2051.4 677.28,2051.4 712.57,2016.11 1007.36,2016.11 v1(1027.09,1996.38)
LED_A0: R271.2 R274.2 U48.9 | length 166.8
  Top Layer w5.3: R274.2@1804.55,1589.85 R271.2@1804.55,1654.54 1835,1654.54 1844.54,1645 U48.9@1902.72,1645
LED_A1: R270.2 R276.2 U48.10 | length 198.7
  Top Layer w5.3: R276.2@1804.55,1466.57 R270.2@1804.55,1526.88 1804.55,1547.41 1852.14,1595 U48.10@1902.72,1595
LED_A2: R269.2 R275.2 U48.7 | length 157.7
  Top Layer w5.3: U48.7@2117.28,1595 2170,1595 2183.45,1581.55 R269.2@2214.39,1581.55 R275.2@2214.39,1526.55
LED_ANODE0: D7.2 R262.1 | length 60
  Top Layer w5.3: R262.1@2459.29,2089.8 D7.2@2519.29,2089.8
LED_ANODE1: D8.2 R263.1 | length 60
  Top Layer w5.3: R263.1@2319.29,2089.8 D8.2@2379.29,2089.8
LED_ANODE2: D9.2 R264.1 | length 60
  Top Layer w5.3: R264.1@2179.29,2089.8 D9.2@2239.29,2089.8
LED_ANODE3: D10.2 R266.1 | length 60
  Top Layer w5.3: R266.1@2039.29,2089.8 D10.2@2099.29,2089.8
LED_ANODE4: D11.2 R267.1 | length 60
  Top Layer w5.3: R267.1@1867.87,2089.8 D11.2@1927.87,2089.8
LED_ANODE5: D12.2 R273.1 | length 60
  Top Layer w5.3: R273.1@1727.87,2089.8 D12.2@1787.87,2089.8
LED_ANODE6: D13.2 R277.1 | length 60
  Top Layer w5.3: R277.1@1587.87,2089.8 D13.2@1647.87,2089.8
LED_ANODE7: D14.2 R279.1 | length 60
  Top Layer w5.3: R279.1@1467.87,2089.8 D14.2@1527.87,2089.8
LED_DRAIN0: D7.1 U48.3 | length 868.3
  Top Layer w5.3: U48.3@2117.28,1395 2236.68,1395 2353.45,1511.76 2353.45,1735.57 2400,1782.12 2400,1907.52 D7.1@2519.29,2026.81
LED_DRAIN1: D8.1 U48.4 | length 801.9
  Top Layer w5.3: U48.4@2117.28,1445 2264.99,1445 2340,1520.01 2340,1680 2309.75,1710.25 2309.75,1957.27 D8.1@2379.29,2026.81
LED_DRAIN2: D9.1 U48.5 | length 757.1
  Top Layer w5.3: U48.5@2117.28,1495 2294.38,1495 2325,1525.62 2325,1669.57 2298.33,1696.24 2298.33,1967.78 D9.1@2239.29,2026.81
LED_DRAIN3: D10.1 U48.6 | length 532.3
  Top Layer w5.3: D10.1@2099.29,2026.81 2104.1,2022 2104.1,1735 2075,1705.9 2075,1555 2085,1545 U48.6@2117.28,1545
LED_DRAIN4: D11.1 U48.11 | length 1267.1
  Top Layer w5.3: U48.11@1902.72,1545 1856.11,1545 1831.63,1520.52 1831.63,1438.91 1808.52,1415.79 1587.9,1415.79 1574.73,1428.96 1574.73,1675.08 1642.67,1743.02 1761.26,1743.02 1801.2,1782.96 1801.2,1932.06 1841.5,1972.36 1873.42,1972.36 D11.1@1927.87,2026.81
LED_DRAIN5: D12.1 U48.12 | length 1122
  Top Layer w5.3: D12.1@1787.87,2026.81 1700.57,1939.51 1700.57,1782.87 1671.32,1753.62 1638.27,1753.62 1563.63,1678.98 1563.63,1425.07 1583.51,1405.19 1812.91,1405.19 1847.72,1440 1847.72,1480.05 1862.67,1495 U48.12@1902.72,1495
LED_DRAIN6: D13.1 U48.13 | length 1026.8
  Top Layer w5.3: D13.1@1647.87,2026.81 1605.18,1984.11 1605.18,1735.52 1553.03,1683.37 1553.03,1420.68 1579.12,1394.59 1817.3,1394.59 1867.71,1445 U48.13@1902.72,1445
LED_DRAIN7: D14.1 U48.14 | length 1013.3
  Top Layer w5.3: D14.1@1527.87,2026.81 1505.47,2004.4 1505.47,1753.21 1541.94,1716.74 1541.94,1416.78 1574.73,1383.99 1821.69,1383.99 1832.7,1395 U48.14@1902.72,1395
MDIO_CLOCK: U17.10 U22.42 U37.42 | length 3365.5
  SIG 1 w4.75: v1(4754.79,844.9) 4813.87,785.83 4857.97,785.83 4863.01,790.86 5020.43,790.86 5037.78,808.21 5037.78,1027.47 5093.35,1083.04 5322.76,1083.04 5436.94,1197.22 5702.01,1197.22 5829.23,1070 6330.14,1070 v1(6356.28,1043.86) 6400.14,1000 6453.81,1000 6473.81,1020 6473.81,1270.69 6460,1284.5 6460,1415.56 6478.35,1433.91 6478.35,1603.39 6465.77,1615.97 6465.77,1675.59 6465.88,1675.71 6465.88,1682.46 v1(6468.42,1685)
  Bottom Layer w5.3: U17.10@4705.28,854.38 4745.34,854.38 v1(4754.79,844.9) ; v1(6356.28,1043.86) 6359.71,1043.86 6364.05,1039.52 6458.82,1039.52 6489.52,1008.82 6489.52,754.83 6465.33,730.64 U22.42@6465.33,703.9 ; U37.42@6465.33,1653.9 6465.33,1681.92 v1(6468.42,1685)
MDIO_DATA: U17.6 U22.41 U37.41 | length 2995
  SIG 1 w4.75: v1(4751.64,950.33) 4762.39,939.58 4899.06,939.58 4928.8,909.84 4970,909.84 5025.83,965.67 5025.83,1037.22 5081.71,1093.09 5318.59,1093.09 5432.78,1207.27 5706.17,1207.27 5833.39,1080.05 6350.38,1080.05 6410.43,1020 v1(6428.11,1020) 6463.76,1055.64 6463.76,1219.54 6428.11,1255.18 6428.11,1610.77 v1(6445.65,1628.31)
  Bottom Layer w5.3: U17.6@4705.28,933.12 4734.43,933.12 v1(4751.64,950.33) ; v1(6428.11,1020) 6428.11,874.27 6459.52,842.86 6459.52,763.29 6449.52,753.29 6449.52,726.91 6445.65,723.04 U22.41@6445.65,703.9 ; v1(6445.65,1628.31) U37.41@6445.65,1653.9
MUX_EN_GPIO58_INV: R96.2 U46.4 U49.15 U51.15 | length 2798.2
  Top Layer w5.3: U51.15@4392.2,1541.89 4428.14,1541.89 4447.08,1522.95 4543.45,1522.95 4553.5,1533 v1(4553.5,1561.5) ; U49.15@5727.2,739.2 5774.04,739.2 v1(5781,732.24) 5796.5,716.74 5796.5,658.04 5808.17,646.38 R96.2@5836.5,646.38 5862.17,620.71 U46.4@5904.41,620.71
  Bottom Layer w5.3: v1(4553.5,1561.5) 4617.5,1625.5 4923.5,1625.5 5053,1755 5662.77,1755 5772.73,1645.04 5817.41,1645.04 5830,1632.45 5830,1325.93 5823.99,1319.91 5823.99,1229.01 5833.45,1219.55 5833.45,850.26 5781,797.81 v1(5781,732.24)
NetC222_1: C222.1 R246.1 R247.1 | length 238.7
  Top Layer w5.3: v1(6771.84,51.12) 6790,69.27 C222.1@6790,91.38
  SIG 1 w5.3: v1(6771.84,-77.62) v1(6771.84,51.12)
  Bottom Layer w5.3: v1(6771.84,-77.62) 6772.14,-77.91 R246.1@6802.8,-77.91 ; v1(6771.84,51.12) 6772.14,50.83 R247.1@6802.8,50.83
NetD2_2: D2.2 R257.1 | length 75.9
  Top Layer w5.3: D2.2@1748.27,820.2 1748.27,799.12 1768.27,779.12 R257.1@1768.27,752.63
NetD3_2: D3.2 R259.1 | length 54.4
  Top Layer w5.3: D3.2@144.52,1564.76 145.9,1563.38 R259.1@198.34,1563.38
NetD4_2: D4.2 R313.1 | length 67.3
  Top Layer w5.3: R313.1@2595.47,2093.74 D4.2@2662.72,2093.74
NetD5_1: D5.1 Q13.3 | length 68.9
  Top Layer w5.3: Q13.3@1817.4,-26.61 D5.1@1886.27,-26.61
NetD5_2: D5.2 R314.1 | length 68
  Top Layer w5.3: D5.2@1886.27,-89.6 1951.71,-89.6 R314.1@1953.52,-87.79
NetD6_2: D6.2 R315.1 | length 55
  Top Layer w5.3: D6.2@2762.99,-26.84 2763.24,-26.59 R315.1@2817.87,-26.59
NetDS1_1: DS1.1 Q10.2 | length 98.7
  Top Layer w5.3: DS1.1@2584.5,1842.4 2617.4,1842.4 2643.4,1868.4 Q10.2@2672.41,1868.4
NetDS1_2: DS1.2 R265.1 | length 81.8
  Top Layer w5.3: R265.1@2505.77,1767.12 2505.77,1796.53 2521.5,1812.26 DS1.2@2521.5,1842.4
NetDS2_1: DS2.1 Q11.3 | length 67.7
  Top Layer w5.3: Q11.3@5715.4,1915.27 5741.41,1915.27 5747.32,1909.36 DS2.1@5780.69,1909.36
NetDS2_2: DS2.2 R302.1 | length 70
  Top Layer w5.3: DS2.2@5780.69,1972.36 5848.4,1972.36 R302.1@5850,1973.95
NetDS3_2: DS3.2 R260.1 | length 64.8
  Top Layer w5.3: DS3.2@144.52,1647.79 158.93,1633.38 R260.1@203.34,1633.38
NetL4_1: L4.1 U36.9 | length 18.6
  Top Layer w12: U36.9@2755.12,160.75 2773.75,160.75
NetQ10_1: Q10.1 R272.2 | length 131.2
  Top Layer w5.3: Q10.1@2723.59,1868.4 2741.6,1868.4 2785.31,1824.69 R272.2@2785.31,1773.35
NetQ11_1: Q11.1 R303.2 | length 55.9
  Top Layer w5.3: R303.2@5584.69,1940.86 Q11.1@5640.6,1940.86
NetQ13_1: Q13.1 R317.2 | length 69
  Top Layer w5.3: R317.2@1689.67,-22.51 1689.67,-10.33 1698.98,-1.02 Q13.1@1742.6,-1.02
NetR8_2: R8.2 U4.4 U4.5 | length 145.4
  Bottom Layer w5.3: R8.2@3436.76,-40.23 3436.45,-39.91 3436.45,8.78 3441.82,14.16 U4.5@3468.83,14.16 3468.83,-3.69 3477.93,-12.8 3487.86,-12.8 3492.45,-8.21 U4.4@3492.45,6.28
NetR22_2: R22.2 SW1.1 | length 84.4
  Top Layer w12: SW1.1@3662.01,-30.49 R22.2@3746.38,-30.49
NetR23_2: R23.2 SW1.2 | length 84.4
  Top Layer w12: SW1.2@3662.01,19.51 R23.2@3746.38,19.51
NetR24_2: R24.2 SW1.3 | length 84.4
  Top Layer w12: SW1.3@3662.01,69.51 R24.2@3746.38,69.51
NetR25_2: R25.2 SW1.4 | length 84.4
  Top Layer w12: SW1.4@3662.01,119.51 R25.2@3746.38,119.51
NetR245_2: R245.2 U42.1 | length 77.9
  Bottom Layer w5.3: U42.1@6977.91,24.84 6995.98,24.84 7005,33.86 7005,51.46 7015,61.46 R245.2@7030.31,61.46
NetR249_2: R249.2 U42.4 | length 81.8
  Bottom Layer w5.3: U42.4@6977.91,-51.93 6997.67,-51.93 7003.38,-57.64 7003.38,-81.92 7010,-88.54 R249.2@7030.31,-88.54
NetR256_2: R256.2 U52.18 U52.19 U52.20 U52.21 | length 504.7
  Top Layer w5.3: U52.21@4385.47,693.23 4385.47,735.47 4395.28,745.28 4415,745.28 ; U52.20@4405.16,693.23 4405.16,735.44 4415,745.28 ; U52.19@4424.84,693.23 4424.84,738.3 4431.82,745.28 ; U52.18@4444.53,693.23 4444.53,745.28 ; R256.2@4666.77,711.65 4633.14,745.28 4444.53,745.28 ; 4415,745.28 4431.82,745.28 ; 4431.82,745.28 4444.53,745.28
NetU10_4: U10.4 U11.5 | length 141.4
  Top Layer w5.3: U10.4@671.92,444.53 707.03,444.53 732.5,470 U11.5@802.76,470
PG_VDD_1V2: R295.1 R317.1 U2.3 U29.5 | length 2317.9
  Top Layer w5.3: v1(1446.64,289.27) 1512.04,223.87 1512.04,62.44 1596.99,-22.51 R317.1@1650.3,-22.51 ; U2.3@1817.11,1092.05 1817.11,1014.31 R295.1@1816.38,1013.59 1816.38,990 1828.86,977.52 v1(1905,977.52)
  Top Layer w10: v1(2263.01,810) 2271.49,801.52 U29.5@2291.44,801.52
  SIG 1 w5.3: v1(1446.64,289.27) 1641.8,484.43 1770.83,484.43 1830.18,543.77 1830.18,688.97 1757.54,761.6 1757.54,802.75 1778.97,824.18 1866.04,824.18 1890.84,848.98 1890.84,876.01 1874.39,892.47 1874.39,946.91 v1(1905,977.52) 1967,1039.52 2213.09,1039.52 2263.01,989.6 v1(2263.01,810)
PG_VSYS_3V3: R296.1 U2.6 U32.5 | length 1032.4
  Top Layer w5.3: U2.6@1925.37,1166.85 1953.52,1166.85 1970.87,1184.19 1970.87,1200.49 1985.38,1215 R296.1@2002.79,1215 2002.79,1194.27 2037.27,1159.78 2281.62,1159.78 2340,1218.16 v1(2340,1334.99)
  Top Layer w10: v1(2624.69,1442.62) 2633.16,1434.14 U32.5@2653.11,1434.14
  SIG 1 w4.75: v1(2340,1334.99) 2340,1422.16 2360.46,1442.62 v1(2624.69,1442.62)
PORZ_DELAY: U5.2 U6.4 | length 86.3
  Top Layer w5.3: U6.4@1914.38,627.98 1914.38,655.35 1931.31,672.28 U5.2@1931.31,707.27
PORZ_PB: Q1.2 R177.1 SW2.2 SW2.4 U34.1 | length 936.2
  Top Layer w4: U34.1@528.78,1996.97 541.97,1996.97 v1(550,2005)
  Top Layer w5.3: SW2.2@217.32,2102.28 SW2.4@437.8,2102.28 476.9,2102.28 550,2029.18 v1(550,2005)
  SIG 1 w5.3: v1(550,2005) 553.3,2005 559.45,2011.16 648.67,2011.16 819.83,1840 v1(850,1840)
  Bottom Layer w5.3: Q1.2@740.38,1805 774.75,1805 782.5,1797.24 R177.1@816.87,1797.24 842.2,1797.24 850,1805.04 v1(850,1840)
PR0_PRU0_GPIO0: R360.1 U23.2 | length 113.3
  Top Layer w5.3: R360.1@4523.6,1480.95 4542.8,1480.95 4551.25,1472.5 4551.25,1456.33 4563.31,1444.27 U23.2@4612.24,1444.29
PR0_PRU0_GPIO0_MUX: J2/J4.33 U23.42 | length 2981.1
  Top Layer w5.3: U23.42@4647.68,1479.73 v1(4647.68,1539)
  SIG 1 w4.75: J2/J4.33@2154.17,1800 2208.13,1853.95 2293.91,1853.95 2294.77,1854.81 2386.25,1854.81 2400.79,1869.35 2848.43,1869.35 2883.3,1834.48 3096.07,1834.48 3178.44,1916.84 3178.44,1927.33 3287.45,2036.34 4185.44,2036.34 4298.08,1923.7 4298.08,1771.11 4320,1749.19 4437.49,1749.19 v1(4647.68,1539)
PR0_PRU0_GPIO0_R: R360.2 U1.K17 | length 1430.6
  Top Layer w4: U1.K17@3901.07,949.33 3918.69,931.71 3950.24,931.71
  Top Layer w5.3: 3950.24,931.71 4100.25,931.71 4112.28,943.74 4219.44,943.74 4232.6,956.9 4335.81,956.9 4354.17,975.26 4378.92,975.26 4403.2,999.54 4600.87,999.54 v1(4632,1030.67) ; v1(4447.39,1471.89) 4450.83,1471.89 4460.22,1481.27 R360.2@4483.91,1481.27
  Bottom Layer w5.3: v1(4447.39,1471.89) 4448.52,1473.02 4484.68,1473.02 4598.18,1359.52 4598.34,1359.36 4598.34,1323.28 4624.88,1296.75 4624.88,1189.88 4684.83,1129.93 4684.83,1041.39 4672.38,1028.93 4633.74,1028.93 v1(4632,1030.67)
PR0_PRU0_GPIO1: R361.1 U23.3 | length 98.4
  Top Layer w5.3: R361.1@4523.28,1447.48 4523.4,1447.37 4539.94,1447.37 4562.7,1424.61 U23.3@4612.24,1424.61
PR0_PRU0_GPIO1_MUX: J2/J4.32 U23.40 | length 2967.1
  Top Layer w5.3: U23.40@4687.05,1479.73 4687.05,1516.14 v1(4710.91,1540)
  SIG 1 w4.75: J2/J4.32@2254.17,1800 2298.94,1844.76 2392.11,1844.76 2406.65,1859.3 2844.27,1859.3 2879.14,1824.43 3100.24,1824.43 3188.49,1912.68 3188.49,1923.17 3291.61,2026.29 4113.19,2026.29 4210.27,1929.21 4210.27,1773.86 4245,1739.14 4413.86,1739.14 4636,1517 4687.91,1517 v1(4710.91,1540)
PR0_PRU0_GPIO1_R: R361.2 U1.K18 | length 1446.7
  Top Layer w5.3: U1.K18@3932.57,949.33 3933.04,949.81 3943.87,949.81 3948.4,954.34 4209.92,954.34 4223.08,967.5 4328.77,967.5 4350,988.73 4376.72,988.73 4398.12,1010.14 4581.74,1010.14 4632.99,1061.39 v1(4632.99,1062.68) ; v1(4454.34,1445.69) 4456.47,1447.82 R361.2@4483.57,1447.82
  Bottom Layer w5.3: v1(4454.34,1445.69) 4469.74,1461.08 4476.56,1461.08 4483.28,1454.36 4483.28,1449.97 4470.94,1437.63 4470.94,1428.74 4474.93,1424.76 4484.63,1424.76 4495.38,1435.51 4507.2,1435.51 4587.55,1355.16 4587.74,1354.97 4587.74,1318.89 4614.28,1292.36 4614.28,1148.26 4617.44,1145.1 4654.22,1145.1 4674.23,1125.09 4674.23,1108.1 4671.13,1105 4661.3,1105 4640.16,1126.14 4617.79,1126.14 4614.33,1122.68 4614.33,1095.38 4630.56,1079.15 4630.56,1065.11 v1(4632.99,1062.68)
PR0_PRU0_GPIO2: R362.1 U23.4 | length 92.7
  Top Layer w5.3: R362.1@4523.21,1413.86 4547.05,1413.86 4555.99,1404.92 U23.4@4612.24,1404.92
